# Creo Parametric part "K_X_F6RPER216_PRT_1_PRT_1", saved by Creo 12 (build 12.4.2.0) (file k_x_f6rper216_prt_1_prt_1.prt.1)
Units: Custom; MM, KILOGRAM, SECS

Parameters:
  PTC_WM_ITERATION = "0"
  PTC_WM_VERSION = "-.0"
  PTC_WM_LIFECYCLE_STATE = "In Work"
  PTC_WM_LIFECYCLE = "MO_CADDocument"
  PTC_WM_CREATED_BY = "Maximilian Roepper (Z0017RMS: MO)"
  PTC_WM_CREATED_ON = "18-Sep-26 11:36:42 AM"
  PTC_WM_MODIFIED_BY = "Maximilian Roepper (Z0017RMS: MO)"
  PTC_WM_MODIFIED_ON = "18-Sep-26 11:36:46 AM"
  PDMLINKNUMBER = "PDM000071455132"
  PTC_WM_NAME = "k_x_f6rper216_prt_1_prt_1.prt"
  PTC_WM_NUMBER = "PDM000071455132"

Other parameters: WEIGHT, WEIGHT_FACTOR, WEIGHT_ADD, _MASS_TEMP, _DIFF_TEMP, MC_ERRORS, SUPPLIER

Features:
  1. coordinate system
  2. datum plane "PRT_YZ"
  3. datum plane "PRT_XY"
  4. datum plane "PRT_XZ"
  5. coordinate system
  6. datum axis
  7. datum axis
  8. datum axis
  9. coordinate system
  10. imported feature
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
Other named items: PRT, SIEMENS_MO, DRW_VIEW_ORG, PRT_X, PRT_Y, PRT_Z, CS0, ROUGH_GROB

Layers: 00_STD_CSYS-KSYS, 01_STD_PLANES-EBENEN, 02_STD_AXES-ACHSEN, 03_STD_CSYS-KSYS, 24_IMPORT_FEAT-IMPORT_KE

Surfaces: 16 tabulated cylinder, 8 plane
